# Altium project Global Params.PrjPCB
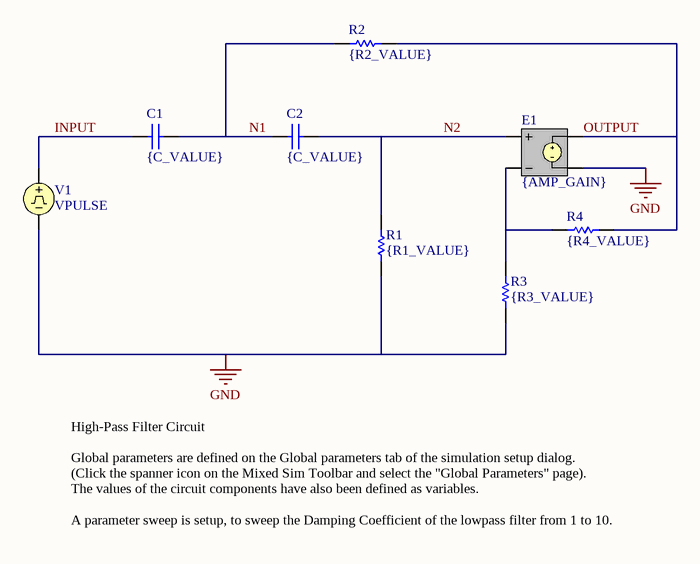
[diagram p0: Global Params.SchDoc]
1 sheet, 8 parts. Net scope: global (net labels, ports and power ports of the same name join across sheets).

## Sheet Global Params.SchDoc: Global Parameters
size A; DocumentNumber: 1; SheetNumber: 1; SheetTotal: 1

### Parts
C1  value {C_VALUE}  [RAD-0.3]  (hidden comment: Cap)
C2  value {C_VALUE}  [RAD-0.3]  (hidden comment: Cap)
E1  Gain: {AMP_GAIN}  (hidden comment: ESRC)
R1  value {R1_VALUE}  [AXIAL-0.3]  (hidden comment: Res1)
R2  value {R2_VALUE}  [AXIAL-0.3]  (hidden comment: Res1)
R3  value {R3_VALUE}  [AXIAL-0.3]  (hidden comment: Res1)
R4  value {R4_VALUE}  [AXIAL-0.3]  (hidden comment: Res1)
V1  VPULSE

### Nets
GND: E1.4(N-) R1.1 R3.1 V1.2
INPUT: C1.1 V1.1
N1: C1.2 C2.2 R2.2
N2: C2.1 E1.1(NC+) R1.2
OUTPUT: E1.3(N+) R2.1 R4.1
NetE1_2: E1.2(NC-) R3.2 R4.2

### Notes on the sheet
- High-Pass Filter Circuit
  Global parameters are defined on the Global parameters tab of the simulation setup dialog.
  (Click the spanner icon on the Mixed Sim Toolbar and select the "Global Parameters" page).
  The values of the circuit components have also been defined as variables.
  A parameter sweep is setup, to sweep the Damping Coefficient of the lowpass filter from 1 to 10.

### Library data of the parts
C1 C2 = Cap: Capacitor
E1 = ESRC: Voltage Controlled Voltage Source; Note: PCB Footprint - Not required; Sim Note: Enter gain into gain field
R1-R4 = Res1: Resistor
V1 = VPULSE: Pulse Voltage Source; Note: PCB Footprint - Not required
